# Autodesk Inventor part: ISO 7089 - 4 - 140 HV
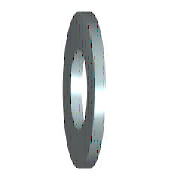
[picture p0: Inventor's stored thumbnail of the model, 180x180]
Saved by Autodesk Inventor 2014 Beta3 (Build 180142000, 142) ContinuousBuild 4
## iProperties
IsCustomPart: 0
Created: 2010-02
Part Number: ISO 7089 - 4 - 140 HV
Material: Stainless Steel
Description: Plain washers - Normal series - Product grade A
Document SubType Name: Modeling
Standard: ISO 7089
Designer: Thom Tremblay
Standard Revision: Second edition 2000-06-01
Standards Organization: ISO
Language: en-US
Size Designation: 4 - 140 HV
Categories: <MemberInstance><Categories><Category DisplayName="Fasteners" InternalName="e4da775c-781d-43d5-af7c-5136215cf5a6" Mnemonic="FSTN"><Category DisplayName="Washers
Density: 8.08 g/cm^3
Appearance: Steel
Author: Thom Tremblay
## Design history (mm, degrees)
sketch "Sketch"
  geometry: C1 r 4.5 at (0, 0); C2 r 2.15 at (0, 0); 1 further point
  constraints: 2 centre point, 2 coincident
  dimensions: "d0" = 4.3 diameter of C2 (= SD1); "d1" = 9 diameter of C1 (= SD2)
extrude "Body" new body sketch "Sketch" distance "d2" = 0.8 (= SD); taper "d3" = 0 deg
workaxis "Work Axis1"
workplane "Work Plane1"
body "Solid1"
other parameters: "SD1" = 4.3 [user parameter; used in 1 equation term], "SD2" = 9 [user parameter; used in 1 equation term], "SD" = 0.8 [user parameter; used in 1 equation term], "d4" = 0, "d5" = 0, "d6" = 0, "d7" = 0, "NND" = 4 [user parameter]
